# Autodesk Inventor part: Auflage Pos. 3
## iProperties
Created: 2009-11
Part Number: Auflage Pos. 3
Document SubType Name: Modeling
Designer: user
Author: user
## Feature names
1. Extrusion1
2. Bohrung1 [Hole]
